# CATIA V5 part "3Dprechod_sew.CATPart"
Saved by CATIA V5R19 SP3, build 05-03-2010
Part number: Tp6016860__0-0.SLDPRT
Bounding box of the stored display mesh (mm): x -200.407 to 167.516, y -155.104 to 63.494, z 0 to 966.074
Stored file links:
  C:\Gmill\Tp6016860_RVT\Model_aktualni_verze_E\3Dprechod_sew.CATPart
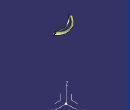
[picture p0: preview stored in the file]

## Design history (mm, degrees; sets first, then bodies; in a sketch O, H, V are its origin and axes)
AxisSystem1: origin (0, 0, 0), X (1, 0, 0), Y (0, 1, 0), Z (0, 0, 1)
Set1
  DatumCurve1 to DatumCurve272
  DatumSurface1 to DatumSurface4
  DatumCurve273 to DatumCurve284
  Join1: Elements (DatumSurface2; DatumSurface1; DatumSurface3; DatumSurface4)
Set2
  Loft1: Sections (DatumCurve24; DatumCurve23; DatumCurve22; DatumCurve21; DatumCurve20; DatumCurve19; DatumCurve18; DatumCurve17; DatumCurve16; DatumCurve15; DatumCurve14; DatumCurve13; DatumCurve12; DatumCurve11; DatumCurve10; DatumCurve9; DatumCurve8; DatumCurve7; DatumCurve6; DatumCurve5; DatumCurve4; DatumCurve3; DatumCurve2; DatumCurve1; DatumCurve28; DatumCurve27; DatumCurve26; DatumCurve25; DatumCurve29; DatumCurve30; DatumCurve31; DatumCurve32; DatumCurve33; DatumCurve34; DatumCurve35; DatumCurve36; DatumCurve37; DatumCurve38; DatumCurve39; DatumCurve40; DatumCurve41; DatumCurve42; DatumCurve43; DatumCurve44; DatumCurve45; DatumCurve46; DatumCurve47; DatumCurve48; DatumCurve49; DatumCurve50; DatumCurve51; DatumCurve52; DatumCurve53; DatumCurve54; DatumCurve55; DatumCurve57; DatumCurve58; DatumCurve56; DatumCurve59; DatumCurve60; DatumCurve61)
  Curve1: Elements (vertex of DatumCurve66; vertex of DatumCurve77; vertex of DatumCurve78; vertex of DatumCurve79; vertex of DatumCurve80; vertex of DatumCurve81; vertex of DatumCurve82; vertex of DatumCurve83; vertex of DatumCurve84; vertex of DatumCurve85; vertex of DatumCurve86; vertex of DatumCurve87)
  Curve2: Elements (vertex of DatumCurve66; vertex of DatumCurve77; vertex of DatumCurve78; vertex of DatumCurve79; vertex of DatumCurve80; vertex of DatumCurve81; vertex of DatumCurve82; vertex of DatumCurve83; vertex of DatumCurve84; vertex of DatumCurve85; vertex of DatumCurve86; vertex of DatumCurve87)
  Loft2: Sections (DatumCurve66; DatumCurve77; DatumCurve78; DatumCurve79; DatumCurve80; DatumCurve81; DatumCurve82; DatumCurve83; DatumCurve84; DatumCurve85; DatumCurve86; DatumCurve87), Guides (Curve1; Curve2)
  Loft3: Sections (DatumCurve87; DatumCurve88; DatumCurve89; DatumCurve90; DatumCurve91; DatumCurve92; DatumCurve94; DatumCurve96; DatumCurve97; DatumCurve99; DatumCurve101; DatumCurve103; DatumCurve105; DatumCurve107; DatumCurve109; DatumCurve110; DatumCurve113; DatumCurve122; DatumCurve119; DatumCurve116; DatumCurve127; DatumCurve124; DatumCurve135; DatumCurve132; DatumCurve139; DatumCurve143; DatumCurve146; DatumCurve150; DatumCurve155; DatumCurve160; DatumCurve165; DatumCurve170; DatumCurve175; DatumCurve179; DatumCurve183; DatumCurve188; DatumCurve193; DatumCurve197; DatumCurve201; DatumCurve206; DatumCurve210; DatumCurve214; DatumCurve218; DatumCurve222; DatumCurve225; DatumCurve227; DatumCurve229; DatumCurve230; DatumCurve231; DatumCurve233; DatumCurve235)
  Curve3: Elements (vertex of DatumCurve24; vertex of DatumCurve249; vertex of DatumCurve250; vertex of DatumCurve251; vertex of DatumCurve252; vertex of DatumCurve253; vertex of DatumCurve254; vertex of DatumCurve255; vertex of DatumCurve256; vertex of DatumCurve257; vertex of DatumCurve258; vertex of DatumCurve259; vertex [face of DatumCurve246 | face of DatumCurve246]; vertex of DatumCurve261; vertex of DatumCurve262; vertex of DatumCurve263; vertex of DatumCurve264; vertex [face of DatumCurve246 | face of DatumCurve246]; vertex of DatumCurve266; vertex of DatumCurve267; vertex of DatumCurve268; vertex of DatumCurve269; vertex of DatumCurve270; vertex of DatumCurve245; vertex of DatumCurve242; vertex of DatumCurve240; vertex of DatumCurve239; vertex of DatumCurve238; vertex of DatumCurve236; vertex of DatumCurve235)
  Curve4: Elements (vertex of DatumCurve24; vertex of DatumCurve249; vertex of DatumCurve250; vertex of DatumCurve251; vertex of DatumCurve252; vertex of DatumCurve253; vertex of DatumCurve254; vertex of DatumCurve255; vertex of DatumCurve256; vertex of DatumCurve257; vertex of DatumCurve258; vertex of DatumCurve259; vertex of DatumCurve260; vertex of DatumCurve261; vertex of DatumCurve262; vertex of DatumCurve263; vertex of DatumCurve264; vertex of DatumCurve265; vertex of DatumCurve266; vertex of DatumCurve267; vertex of DatumCurve268; vertex of DatumCurve269; vertex of DatumCurve270; vertex of DatumCurve245; vertex of DatumCurve244; vertex of DatumCurve243; vertex of DatumCurve242; vertex of DatumCurve241; vertex of DatumCurve240; vertex of DatumCurve239; vertex of DatumCurve238; vertex of DatumCurve236; vertex of DatumCurve235)
  Loft4: Sections (DatumCurve235; DatumCurve245; DatumCurve24), Guides (Curve3; Curve4)
  Curve5: Elements (vertex of DatumCurve61; vertex of DatumCurve62; vertex of DatumCurve63; vertex of DatumCurve64; vertex of DatumCurve65; vertex of DatumCurve75; vertex of DatumCurve74; vertex of DatumCurve73; vertex of DatumCurve72; vertex of DatumCurve71; vertex of DatumCurve70; vertex of DatumCurve69; vertex of DatumCurve68; vertex of DatumCurve67; vertex of DatumCurve66)
  Curve6: Elements (vertex of DatumCurve61; vertex of DatumCurve62; vertex of DatumCurve63; vertex of DatumCurve64; vertex of DatumCurve65; vertex of DatumCurve75; vertex of DatumCurve74; vertex of DatumCurve73; vertex of DatumCurve72; vertex of DatumCurve71; vertex of DatumCurve70; vertex of DatumCurve69; vertex of DatumCurve68; vertex of DatumCurve67; vertex of DatumCurve66)
  Loft5: Sections (DatumCurve61; DatumCurve278; DatumCurve76; DatumCurve75; DatumCurve74; DatumCurve73; DatumCurve72; DatumCurve71; DatumCurve70; DatumCurve69; DatumCurve68; DatumCurve67; DatumCurve66), Guides (Curve5; Curve6)
Body1 (main body)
